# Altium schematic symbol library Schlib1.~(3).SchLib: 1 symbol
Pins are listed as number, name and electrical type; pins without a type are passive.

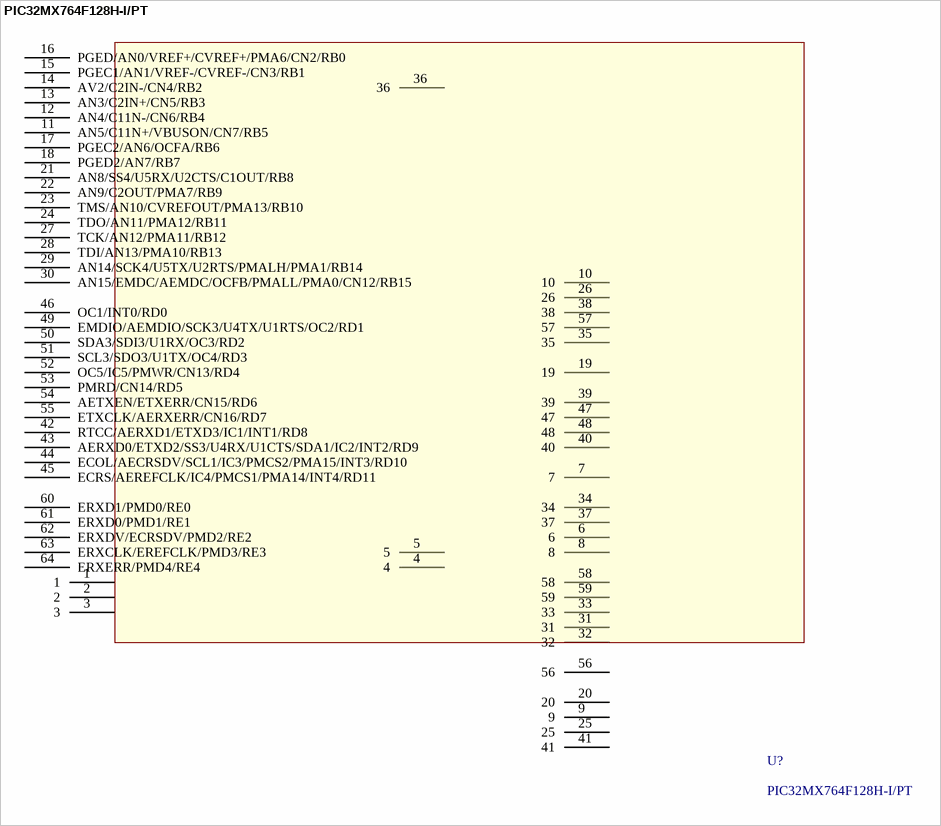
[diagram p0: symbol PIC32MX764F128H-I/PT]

## PIC32MX764F128H-I/PT
designator U?
Fabricant: Microchip; Fournisseur: Farnell; RefFournisseur: 1971889
pins: 1, 2, 3, 4, 5, 6, 7, 8, 9, 10, 11 AN5/C11N+/VBUSON/CN7/RB5, 12 AN4/C11N-/CN6/RB4, 13 AN3/C2IN+/CN5/RB3, 14 AV2/C2IN-/CN4/RB2, 15 PGEC1/AN1/VREF-/CVREF-/CN3/RB1, 16 PGED/AN0/VREF+/CVREF+/PMA6/CN2/RB0, 17 PGEC2/AN6/OCFA/RB6, 18 PGED2/AN7/RB7, 19, 20, 21 AN8/SS4/U5RX/U2CTS/C1OUT/RB8, 22 AN9/C2OUT/PMA7/RB9, 23 TMS/AN10/CVREFOUT/PMA13/RB10, 24 TDO/AN11/PMA12/RB11, 25, 26, 27 TCK/AN12/PMA11/RB12, 28 TDI/AN13/PMA10/RB13, 29 AN14/SCK4/U5TX/U2RTS/PMALH/PMA1/RB14, 30 AN15/EMDC/AEMDC/OCFB/PMALL/PMA0/CN12/RB15, 31, 32, 33, 34, 35, 36, 37, 38, 39, 40, 41, 42 RTCC/AERXD1/ETXD3/IC1/INT1/RD8, 43 AERXD0/ETXD2/SS3/U4RX/U1CTS/SDA1/IC2/INT2/RD9, 44 ECOL/AECRSDV/SCL1/IC3/PMCS2/PMA15/INT3/RD10, 45 ECRS/AEREFCLK/IC4/PMCS1/PMA14/INT4/RD11, 46 OC1/INT0/RD0, 47, 48, 49 EMDIO/AEMDIO/SCK3/U4TX/U1RTS/OC2/RD1, 50 SDA3/SDI3/U1RX/OC3/RD2, 51 SCL3/SDO3/U1TX/OC4/RD3, 52 OC5/IC5/PMWR/CN13/RD4, 53 PMRD/CN14/RD5, 54 AETXEN/ETXERR/CN15/RD6, 55 ETXCLK/AERXERR/CN16/RD7, 56, 57, 58, 59, 60 ERXD1/PMD0/RE0, 61 ERXD0/PMD1/RE1, 62 ERXDV/ECRSDV/PMD2/RE2, 63 ERXCLK/EREFCLK/PMD3/RE3, 64 ERXERR/PMD4/RE4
